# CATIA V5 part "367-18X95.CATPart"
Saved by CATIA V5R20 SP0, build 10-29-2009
Part number: 367-18X95
Definition: NONE
Nomenclature: 367-18X95
Source: Unknown
Description: 367-18X95
Bounding box of the stored display mesh (mm): x 0 to 95, y -14 to 14, z -14 to 14
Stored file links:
  C:\Users\Utente\Desktop\IO LAVORO\3D X SITO CF\X SITO\PLASTICA\3D files 367\367-18X95.CATPart
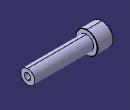
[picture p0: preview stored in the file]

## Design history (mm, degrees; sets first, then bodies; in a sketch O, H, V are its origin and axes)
Body1 "367-18X95" (main body)
  Solid1: solid without history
